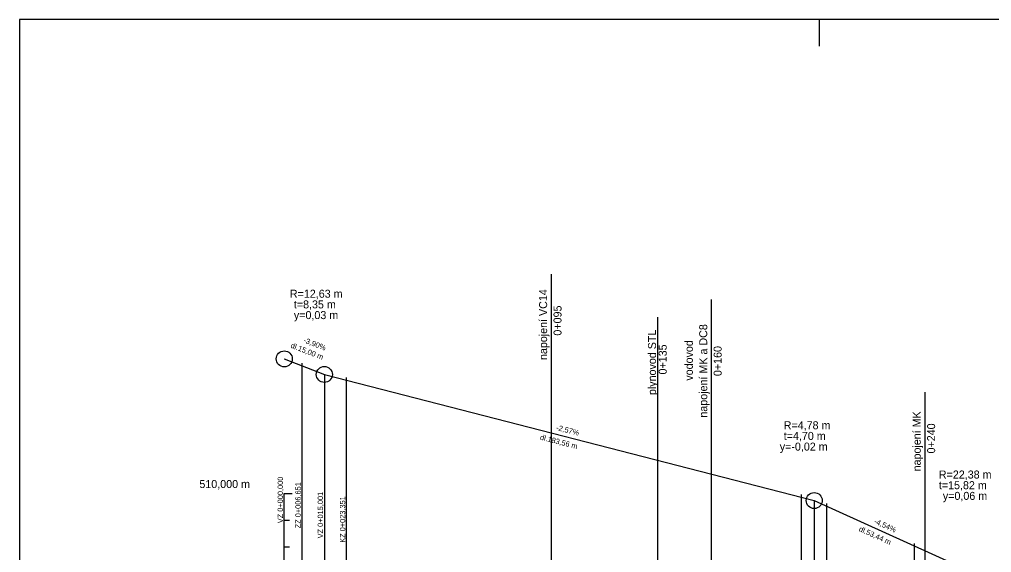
# Model space of a CAD drawing. Extents: x -632716 to -629545, y -1094726 to -1088285.
# Drawn here: x -632543.1 to -632178.9, y -1089158.6 to -1088958.8 of the extents above; entities that cross this region are included whole.
import ezdxf

# ---------------------------------------------------------------- set-up
doc = ezdxf.new("R2010")
doc.units = 0
for name, color, linetype in [('formát', 7, 'Continuous'), ('REZ_POPIS', 7, 'Continuous'), ('REZ_TENKA', 7, 'Continuous'), ('REZ_TLUSTA', 7, 'Continuous'), ('SKLONY_NIVELETA', 7, 'Continuous'), ('SKLONY_POPIS', 7, 'Continuous'), ('TECNY_NIVELETA', 7, 'Continuous')]:
    doc.layers.add(name, color=color, linetype=linetype)

msp = doc.modelspace()

# ---------------------------------------------------------------- linework, layer by layer
at = {"layer": 'formát'}
msp.add_line((-632243.32, -1088968.83), (-632243.32, -1088958.83), dxfattribs=at)
msp.add_lwpolyline([(-632543.13, -1089552.83), (-631403.32, -1089552.83), (-631403.32, -1088958.83), (-632543.13, -1088958.83)], close=True, dxfattribs=at)
at = {"layer": 'REZ_TENKA'}
for p, q in [((-632443.88, -1089436.44), (-632443.88, -1089136.44)), ((-632443.88, -1089146.44), (-632441.88, -1089146.44)), ((-632443.88, -1089156.44), (-632441.88, -1089156.44))]:
    msp.add_line(p, q, dxfattribs=at)
at = {"layer": 'REZ_TLUSTA'}
msp.add_line((-632443.88, -1089136.44), (-632440.88, -1089136.44), dxfattribs=at)
msp.add_line((-632443.88, -1089136.44), (-632440.88, -1089136.44), dxfattribs=at)
at = {"layer": 'SKLONY_NIVELETA'}
for p, q in [((-632343.88, -1089054.35), (-632343.88, -1089213.75)), ((-632283.88, -1089063.8), (-632283.88, -1089229.2)), ((-632443.88, -1089086.03), (-632443.88, -1089086.03)), ((-632443.88, -1089086.03), (-632428.88, -1089091.87)), ((-632428.88, -1089091.87), (-632428.88, -1089436.44)), ((-632428.88, -1089091.87), (-632245.32, -1089139.12)), ((-632203.88, -1089098.51), (-632203.88, -1089257.91)), ((-632245.32, -1089139.12), (-632245.32, -1089436.44)), ((-632245.32, -1089139.12), (-632191.88, -1089163.39))]:
    msp.add_line(p, q, dxfattribs=at)
for centre in [(-632443.88, -1089086.03), (-632428.88, -1089091.87), (-632245.32, -1089139.12)]:
    msp.add_circle(centre, 3, dxfattribs=at)
at = {"layer": 'TECNY_NIVELETA'}
for p, q in [((-632303.88, -1089224.05), (-632303.88, -1089070.43)), ((-632443.88, -1089086.03), (-632443.88, -1089086.03)), ((-632437.23, -1089188.62), (-632437.23, -1089087.62)), ((-632428.88, -1089091.87), (-632428.88, -1089091.87)), ((-632420.53, -1089194.02), (-632420.53, -1089093.02)), ((-632250.02, -1089237.91), (-632250.02, -1089136.91)), ((-632245.32, -1089139.12), (-632245.32, -1089139.12)), ((-632240.62, -1089241.26), (-632240.62, -1089140.26)), ((-632207.7, -1089256.21), (-632207.7, -1089155.21))]:
    msp.add_line(p, q, dxfattribs=at)

# ---------------------------------------------------------------- texts
at = {"layer": 'REZ_POPIS'}
msp.add_text('510,000 m', height=3, dxfattribs=at).set_placement((-632475.7, -1089134.44))
msp.add_text('510,000 m', height=3, dxfattribs=at).set_placement((-632475.7, -1089134.44))
at = {"layer": 'SKLONY_POPIS'}
for s, p in [('R=12,63 m', (-632441.79, -1089063.12)), ('t=8,35 m', (-632440.3, -1089067.12)), ('y=0,03 m', (-632440.3, -1089071.12)), ('R=4,78 m', (-632256.74, -1089112.41)), ('t=4,70 m', (-632256.74, -1089116.41)), ('y=-0,02 m', (-632258.23, -1089120.41)), ('R=22,38 m', (-632198.61, -1089130.87)), ('t=15,82 m', (-632198.61, -1089134.87)), ('y=0,06 m', (-632197.12, -1089138.87))]:
    msp.add_text(s, height=3, dxfattribs=at).set_placement(p)
for s, height, rotation, p in [('napojení VC14', 3, 90, (-632345.4, -1089086.47)), ('0+095', 3, 90, (-632340, -1089077.32)), ('plynovod STL', 3, 90, (-632304.6, -1089099.61)), ('napojení MK a DC8', 3, 90, (-632285.4, -1089108.05)), ('dl.15,00 m', 2, 338.7128, (-632441.71, -1089081.76)), ('-3,90%', 2, 338.7128, (-632436.89, -1089079.8)), ('vodovod', 3, 90, (-632290.8, -1089094.2)), ('0+135', 3, 90, (-632300.6, -1089091.89)), ('0+160', 3, 90, (-632280, -1089092.48)), ('napojení MK', 3, 90, (-632205.4, -1089128.2)), ('-2,57%', 2, 345.565, (-632342.18, -1089112.64)), ('0+240', 3, 90, (-632200, -1089121.48)), ('dl.183,56 m', 2, 345.565, (-632348.23, -1089116.25)), ('VZ 0+000,000', 2, 90, (-632444.38, -1089147.61)), ('ZZ 0+006,651', 2, 90, (-632437.73, -1089149.53)), ('VZ 0+015,001', 2, 90, (-632429.38, -1089153.29)), ('KZ 0+023,351', 2, 90, (-632421.03, -1089154.94)), ('dl.53,44 m', 2, 335.574, (-632228.79, -1089150.48)), ('-4,54%', 2, 335.574, (-632223.11, -1089147.56))]:
    msp.add_text(s, height=height, rotation=rotation, dxfattribs=at).set_placement(p)

doc.saveas('drawing.dxf')
